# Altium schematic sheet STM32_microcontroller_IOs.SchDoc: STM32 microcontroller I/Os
size A4; Date: Not used; ApprovedBy: Not used; CheckedBy: Not used; Author: Not used; CompanyName: STMicroelectronics; DrawnBy: Not used; Engineer: Not used; Organization: Not used; Address1: Not used; Address2: Not used; Address3: Not used; Address4: Not used; DocumentNumber: 3; Revision: Not used; SheetNumber: 3; SheetTotal: 8
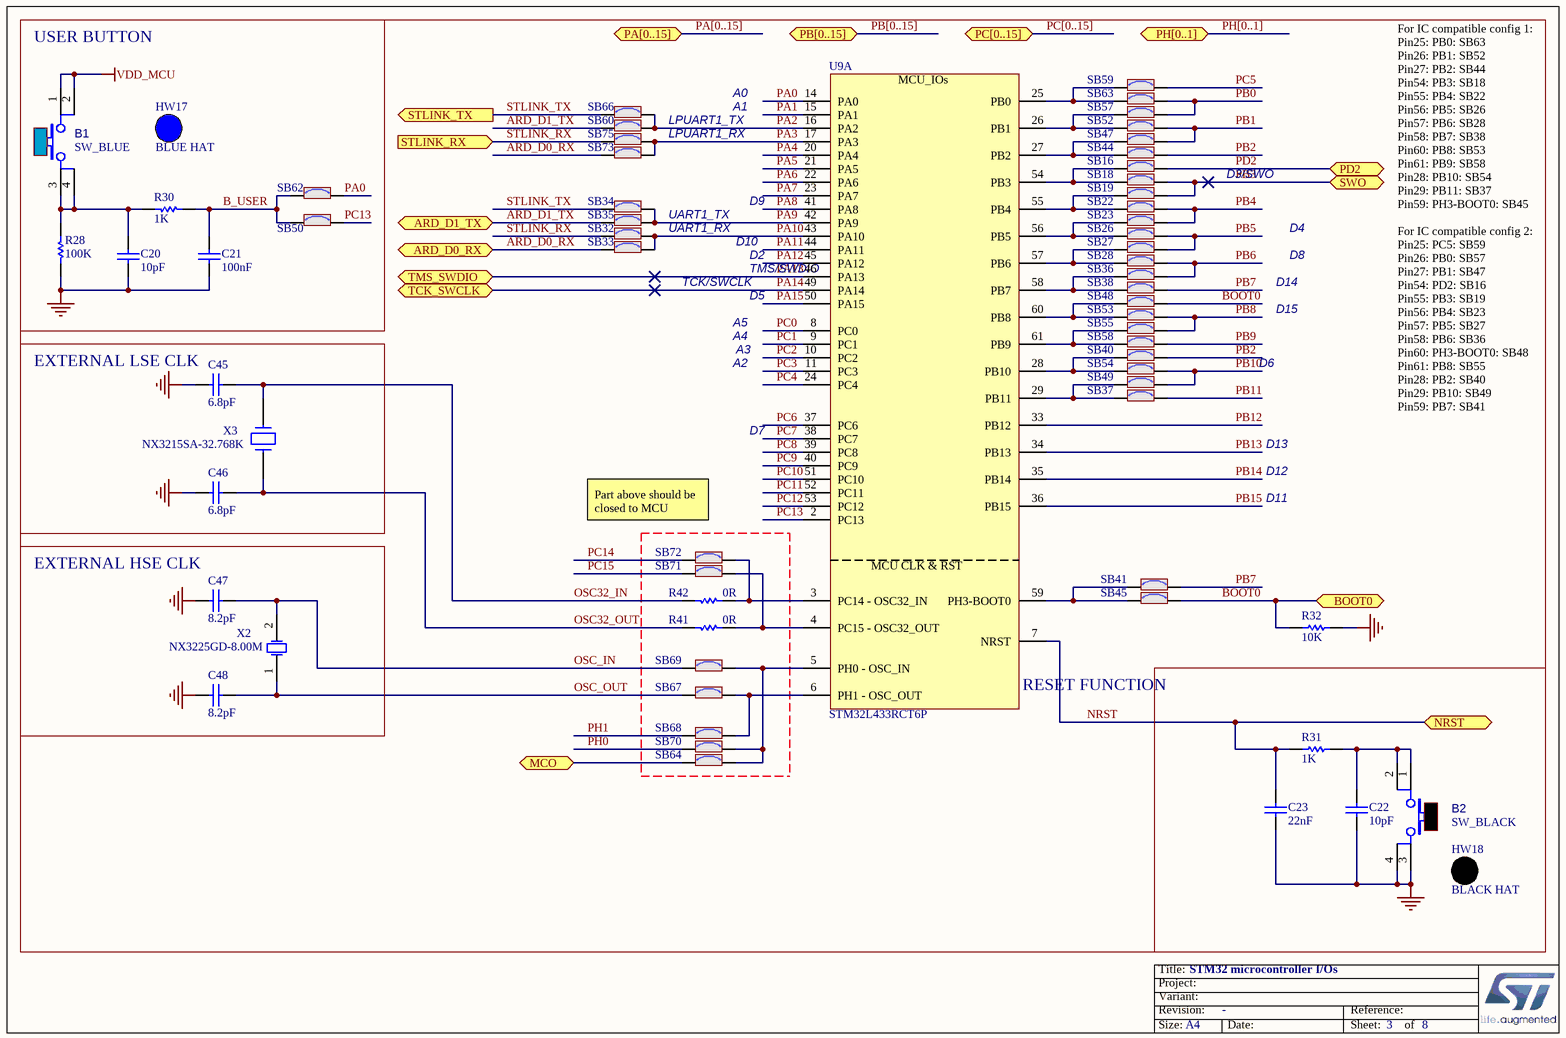
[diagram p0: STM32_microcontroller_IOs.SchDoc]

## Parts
B1  value SW_BLUE  [SWI_WEALTHMETAL_TD-0341_4P_BLUE]  (hidden comment: SW-PUSH-CMS_BLUE)
B2  value SW_BLACK  [SWI_WEALTHMETAL_TD-0341_4P_BLACK]  (hidden comment: SW-PUSH-CMS_BLACK)
C20  value 10pF  [C0603]  (hidden comment: Capacitor)
C21  value 100nF  [C0603]  (hidden comment: Capacitor)
C22  value 10pF  [C0603]  (hidden comment: Capacitor)
C23  value 22nF  [C0603]  (hidden comment: Capacitor)
C45  value 6.8pF  [C0402]  (hidden comment: Capacitor)
C46  value 6.8pF  [C0402]  (hidden comment: Capacitor)
C47  value 8.2pF  [C0402]  (hidden comment: Capacitor)
C48  value 8.2pF  [C0402]  (hidden comment: Capacitor)
HW17  value BLUE HAT  (hidden comment: BUTTON_HAT_BLUE)  (mechanical)
HW18  value BLACK HAT  (hidden comment: BUTTON_HAT_BLACK)  (mechanical)
R28  value 100K  [R0603]  (hidden comment: Resistor)
R30  value 1K  [R0603]  (hidden comment: Resistor)
R31  value 1K  [R0603]  (hidden comment: Resistor)
R32  value 10K  [R0603]  (hidden comment: Resistor)
R41  value 0R  [R0603]  (hidden comment: Resistor)
R42  value 0R  [R0603]  (hidden comment: Resistor)
SB16  SB_ON  [SOLDER-BRIDGE_R0603-0R]  (value not drawn)
SB18  SB_ON  [SOLDER-BRIDGE_R0603-0R]  (value not drawn)
SB19  SB_ON  [SOLDER-BRIDGE_R0603-0R]  (value not drawn)
SB22  SB_ON  [SOLDER-BRIDGE_R0603-0R]  (value not drawn)
SB23  SB_ON  [SOLDER-BRIDGE_R0603-0R]  (value not drawn)
SB26  SB_ON  [SOLDER-BRIDGE_R0603-0R]  (value not drawn)
SB27  SB_ON  [SOLDER-BRIDGE_R0603-0R]  (value not drawn)
SB28  SB_ON  [SOLDER-BRIDGE_R0603-0R]  (value not drawn)
SB32  SB_ON  [SOLDER-BRIDGE_R0603-0R]  (value not drawn)
SB33  SB_ON  [SOLDER-BRIDGE_R0603-0R]  (value not drawn)
SB34  SB_ON  [SOLDER-BRIDGE_R0603-0R]  (value not drawn)
SB35  SB_ON  [SOLDER-BRIDGE_R0603-0R]  (value not drawn)
SB36  SB_ON  [SOLDER-BRIDGE_R0603-0R]  (value not drawn)
SB37  SB_ON  [SOLDER-BRIDGE_R0603-0R]  (value not drawn)
SB38  SB_ON  [SOLDER-BRIDGE_R0603-0R]  (value not drawn)
SB40  SB_ON  [SOLDER-BRIDGE_R0603-0R]  (value not drawn)
SB41  SB_ON  [SOLDER-BRIDGE_R0603-0R]  (value not drawn)
SB44  SB_ON  [SOLDER-BRIDGE_R0603-0R]  (value not drawn)
SB45  SB_ON  [SOLDER-BRIDGE_R0603-0R]  (value not drawn)
SB47  SB_ON  [SOLDER-BRIDGE_R0603-0R]  (value not drawn)
SB48  SB_ON  [SOLDER-BRIDGE_R0603-0R]  (value not drawn)
SB49  SB_ON  [SOLDER-BRIDGE_R0603-0R]  (value not drawn)
SB50  SB_ON  [SOLDER-BRIDGE_R0603-0R]  (value not drawn)
SB52  SB_ON  [SOLDER-BRIDGE_R0603-0R]  (value not drawn)
SB53  SB_ON  [SOLDER-BRIDGE_R0603-0R]  (value not drawn)
SB54  SB_ON  [SOLDER-BRIDGE_R0603-0R]  (value not drawn)
SB55  SB_ON  [SOLDER-BRIDGE_R0603-0R]  (value not drawn)
SB57  SB_ON  [SOLDER-BRIDGE_R0603-0R]  (value not drawn)
SB58  SB_ON  [SOLDER-BRIDGE_R0603-0R]  (value not drawn)
SB59  SB_ON  [SOLDER-BRIDGE_R0603-0R]  (value not drawn)
SB60  SB_ON  [SOLDER-BRIDGE_R0603-0R]  (value not drawn)
SB62  SB_ON  [SOLDER-BRIDGE_R0603-0R]  (value not drawn)
SB63  SB_ON  [SOLDER-BRIDGE_R0603-0R]  (value not drawn)
SB64  SB_ON  [SOLDER-BRIDGE_R0603-0R]  (value not drawn)
SB66  SB_ON  [SOLDER-BRIDGE_R0603-0R]  (value not drawn)
SB67  SB_ON  [SOLDER-BRIDGE_R0603-0R]  (value not drawn)
SB68  SB_ON  [SOLDER-BRIDGE_R0603-0R]  (value not drawn)
SB69  SB_ON  [SOLDER-BRIDGE_R0603-0R]  (value not drawn)
SB70  SB_ON  [SOLDER-BRIDGE_R0603-0R]  (value not drawn)
SB71  SB_ON  [SOLDER-BRIDGE_R0603-0R]  (value not drawn)
SB72  SB_ON  [SOLDER-BRIDGE_R0603-0R]  (value not drawn)
SB73  SB_ON  [SOLDER-BRIDGE_R0603-0R]  (value not drawn)
SB75  SB_ON  [SOLDER-BRIDGE_R0603-0R]  (value not drawn)
U9  STM32L433RCT6P  [ICC_LQFP64_10X10_P050_SOCKET_YAMAICHI_IC149-064-069-B5_NM]  (part A of 2)
X2  value NX3225GD-8.00M  [CRY_NX3225GD_2P]  (hidden comment: XTAL_8M_NX3225GD)
X3  value NX3215SA-32.768K  [CRY_NX3215SA_2P]  (hidden comment: XTAL_32K_NX3215SA)

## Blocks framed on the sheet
USER BUTTON: B1 C20 C21 HW17 R28 R30 SB50 SB62
EXTERNAL LSE CLK: C45 C46 X3
EXTERNAL HSE CLK: C47 C48 X2
RESET FUNCTION: B2 C22 C23 HW18 R31

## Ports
ARD_D0_RX, ARD_D1_TX, BOOT0, MCO, NRST, PA[0..15] (bidir), PB[0..15] (bidir), PC[0..15] (bidir), PD2, PH[0..1] (bidir), STLINK_RX (in), STLINK_TX (out), SWO, TCK_SWCLK, TMS_SWDIO

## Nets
GND: B2.3 B2.4 C20.1 C21.1 C22.1 C23.1 C45.2 C46.2 C47.1 C48.1 R28.1 R32.1
VDD_MCU: B1.1 B1.2
ARD_D0_RX: SB33.2 SB73.2 ; port ARD_D0_RX
ARD_D1_TX: SB35.2 SB60.2 ; port ARD_D1_TX
B_USER: C21.2 R30.1 SB50.1 SB62.1
BOOT0: R32.2 SB45.2 SB48.2 ; port BOOT0
MCO: SB64.1 ; port MCO
NRST: C23.2 R31.1 U9.7(NRST) ; port NRST
OSC32_IN: C45.1 R42.2 X3.1
OSC32_OUT: C46.1 R41.2 X3.2
OSC_IN: C47.2 SB69.1 X2.2(OSC2)
OSC_OUT: C48.2 SB67.1 X2.1(OSC1)
PA0: SB62.2 U9.14(PA0)
PA1: U9.15(PA1)
PA2: SB60.1 SB66.2 U9.16(PA2)
PA3: SB73.1 SB75.2 U9.17(PA3)
PA4: U9.20(PA4)
PA5: U9.21(PA5)
PA6: U9.22(PA6)
PA7: U9.23(PA7)
PA8: U9.41(PA8)
PA9: SB34.2 SB35.1 U9.42(PA9)
PA10: SB32.2 SB33.1 U9.43(PA10)
PA11: U9.44(PA11)
PA12: U9.45(PA12)
PA13: U9.46(PA13) ; port TMS_SWDIO
PA14: U9.49(PA14) ; port TCK_SWCLK
PA15: U9.50(PA15)
PB0: SB57.2 SB63.2
PB1: SB47.2 SB52.2
PB2: SB40.2 SB44.2
PB3: SB18.2 SB19.2 ; port SWO
PB4: SB22.2 SB23.2
PB5: SB26.2 SB27.2
PB6: SB28.2 SB36.2
PB7: SB38.2 SB41.1
PB8: SB53.2 SB55.2
PB9: SB58.2
PB10: SB49.2 SB54.2
PB11: SB37.2
PB12: U9.33(PB12)
PB13: U9.34(PB13)
PB14: U9.35(PB14)
PB15: U9.36(PB15)
PC0: U9.8(PC0)
PC1: U9.9(PC1)
PC2: U9.10(PC2)
PC3: U9.11(PC3)
PC4: U9.24(PC4)
PC5: SB59.2
PC6: U9.37(PC6)
PC7: U9.38(PC7)
PC8: U9.39(PC8)
PC9: U9.40(PC9)
PC10: U9.51(PC10)
PC11: U9.52(PC11)
PC12: U9.53(PC12)
PC13: SB50.2 U9.2(PC13)
PC14: SB72.1
PC15: SB71.1
PD2: SB16.2 ; port PD2
PH0: SB70.1
PH1: SB68.1
STLINK_RX: SB32.1 SB75.1 ; port STLINK_RX
STLINK_TX: SB34.1 SB66.1 ; port STLINK_TX
NetB1_3: B1.3 B1.4 C20.2 R28.2 R30.2
NetB2_1: B2.1 B2.2 C22.2 R31.2
NetR41_1: R41.1 SB71.2 U9.4(PC15_-_OSC32_OUT)
NetR42_1: R42.1 SB72.2 U9.3(PC14_-_OSC32_IN)
NetSB16_1: SB16.1 SB18.1 U9.54(PB3)
NetSB19_1: SB19.1 SB22.1 U9.55(PB4)
NetSB23_1: SB23.1 SB26.1 U9.56(PB5)
NetSB27_1: SB27.1 SB28.1 U9.57(PB6)
NetSB36_1: SB36.1 SB38.1 U9.58(PB7)
NetSB37_1: SB37.1 SB49.1 U9.29(PB11)
NetSB40_1: SB40.1 SB54.1 U9.28(PB10)
NetSB41_2: SB41.2 SB45.1 U9.59(PH3-BOOT0)
NetSB44_1: SB44.1 SB47.1 U9.27(PB2)
NetSB48_1: SB48.1 SB53.1 U9.60(PB8)
NetSB52_1: SB52.1 SB57.1 U9.26(PB1)
NetSB55_1: SB55.1 SB58.1 U9.61(PB9)
NetSB59_1: SB59.1 SB63.1 U9.25(PB0)
NetSB64_2: SB64.2 SB69.2 SB70.2 U9.5(PH0_-_OSC_IN)
NetSB67_2: SB67.2 SB68.2 U9.6(PH1_-_OSC_OUT)

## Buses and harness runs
bus PA[0..15] = port PA[0..15]
bus PB[0..15] = port PB[0..15]
bus PC[0..15] = port PC[0..15]
bus PH[0..1] = port PH[0..1]

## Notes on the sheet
- A0
- A1
- LPUART1_TX
- LPUART1_RX
- D3/SWO
- UART1_RX
- UART1_TX
- D10
- D9
- D4
- For IC compatible config 1:
  Pin25: PB0: SB63
  Pin26: PB1: SB52
  Pin27: PB2: SB44
  Pin54: PB3: SB18
  Pin55: PB4: SB22
  Pin56: PB5: SB26
  Pin57: PB6: SB28
  Pin58: PB7: SB38
  Pin60: PB8: SB53
  Pin61: PB9: SB58
  Pin28: PB10: SB54
  Pin29: PB11: SB37
  Pin59: PH3-BOOT0: SB45
- TCK/SWCLK
- D2
- D5
- TMS/SWDIO
- D14
- D15
- D8
- A3
- A2
- A4
- A5
- D6
- D7
- D13
- For IC compatible config 2:
  Pin25: PC5: SB59
  Pin26: PB0: SB57
  Pin27: PB1: SB47
  Pin54: PD2: SB16
  Pin55: PB3: SB19
  Pin56: PB4: SB23
  Pin57: PB5: SB27
  Pin58: PB6: SB36
  Pin60: PH3-BOOT0: SB48
  Pin61: PB8: SB55
  Pin28: PB2: SB40
  Pin29: PB10: SB49
  Pin59: PB7: SB41
- Part above should be closed to MCU
- D12
- D11

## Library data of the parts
B1 = MCD-00002: Non-Open Push-Button 0.1A 24V; Manufacturer_Part_Number: TD0341X-G01-BLU; Manufacturer: WEALTHMETAL; Alternate_Manufacturer_Part_Number: 535-930; Alternate_Manufacturer: FARNELL; Part_Type: Misc; Provided_By: Subcon; Initial_Board_Reference: mb1274
B2 = MCD-00001: Non-Open Push-Button 0.1A 24V; Manufacturer_Part_Number: TD0341X-G01-BLA; Manufacturer: WEALTHMETAL; Alternate_Manufacturer_Part_Number: 535-930; Alternate_Manufacturer: FARNELL; Part_Type: Misc; Provided_By: Subcon; Initial_Board_Reference: mb1274
C20 C22 = MCD-00637: Capacitor,10pF,50V,NPO,5%,0603; Manufacturer_Part_Number: CC0603JRNPO9BN100; Manufacturer: YAGEO; Provided_By: subcon; Initial_Board_Reference: mb1319
C21 = MCD-00237: Capacitor,100nF,6V3,X5R,10%,0603; Manufacturer_Part_Number: CC0603KRX5R5BB104; Manufacturer: YAGEO; Provided_By: Subcon; Initial_Board_Reference: mb1319
C23 = MCD-00555: Capacitor,22nF,10%,25V,X7R,0603; Manufacturer_Part_Number: CC0603KRX7R8BB223; Manufacturer: YAGEO; Provided_By: Subcon; Initial_Board_Reference: mb1331
C45 C46 = MCD-00674: Capacitor, MLCC, 6.8pF, 50V, NPO, +-0.25pF, 0402, T=0.5mm; Manufacturer_Part_Number: CC0402CRNPO9BN6R8; Manufacturer: YAGEO; Provided_By: Subcon; Initial_Board_Reference: mb1319
C47 C48 = MCD-00004: Capacitor,8.2pF,50V,NPO,4%,0402; Manufacturer_Part_Number: 04025A8R2CAT2A; Manufacturer: AVX; Provided_By: Subcon; Initial_Board_Reference: mb1274
HW17 = MCD-00634: Blue Hat for switch TD0341X-G01-BLU; Part_Type: Mechanical; Manufacturer_Part_Number: 988.16.09.3.00002_SH-517; Manufacturer: JIUBABA; Provided_By: Subcon; Initial_Board_Reference: mb1319
HW18 = MCD-00635: Black Hat for switch TD0341X-G01-BLA; Part_Type: Mechanical; Manufacturer_Part_Number: 988.16.09.3.00003_SH-517; Manufacturer: JIUBABA; Provided_By: Subcon; Initial_Board_Reference: mb1319
R28 = MCD-00223: Resistor,100K,0603,1%,1/10W; Manufacturer_Part_Number: RC0603FR-07100KL; Manufacturer: YAGEO; Provided_By: Subcon; Initial_Board_Reference: mb1319
R30 R31 = MCD-00070: Resistor,1K,0603,1%,1/10W; Manufacturer_Part_Number: RC0603FR-071KL; Manufacturer: YAGEO; Provided_By: Subcon; Initial_Board_Reference: mb1274
R32 = MCD-00220: Resistor,10K,0603,1%,1/10W; Manufacturer_Part_Number: RC0603FR-0710KL; Manufacturer: YAGEO; Provided_By: Subcon; Initial_Board_Reference: mb1319
R41 R42 = MCD-00056: Resistor,0R,0603,5%,1/10W; Manufacturer_Part_Number: RC0603JR-070RL; Manufacturer: YAGEO; Provided_By: subcon; Initial_Board_Reference: mb1274
SB16 SB18 SB19 SB22 SB23 SB26-SB28 SB32-SB38 SB40 SB41 SB44 SB45 SB47-SB50 SB52-SB55 SB57-SB60 SB62-SB64 SB66-SB73 SB75 = MCD-00071: Solder Bridge ON; Part_Type: Mechanical; Provided_By: Subcon; Initial_Board_Reference: mb1274
U9 = MCD-00548: Little ORCA 256_STM32L433P External SMPS configuration. LQFP64 package; Part_Type: IC; Manufacturer: STMICROELECTRONICS; ECCN_US: 3A991A2; ECCN_EU: NEC; Provided_By: STM; Initial_Board_Reference: mb1319
X2 = MCD-00092: Crystal 8Mhz, 8pF, -+50PPM, SMD; Manufacturer_Part_Number: NX3225GD 8MHz EXS00A-CG04874; Manufacturer: NDK; Part_Type: Crystal_Osc; ECCN_US: EAR99; ECCN_EU: NEC; Provided_By: STM; Initial_Board_Reference: mb1274
X3 = MCD-00091: Crystal 32.768kHz, 6pF, -+20PPM, R=50K, SMD; Manufacturer_Part_Number: NX3215SA 32.768KHz EXS00A-MU00525; Manufacturer: NDK; Part_Type: Crystal_Osc; ECCN_US: EAR99; ECCN_EU: NEC; Provided_By: STM; Initial_Board_Reference: mb1274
